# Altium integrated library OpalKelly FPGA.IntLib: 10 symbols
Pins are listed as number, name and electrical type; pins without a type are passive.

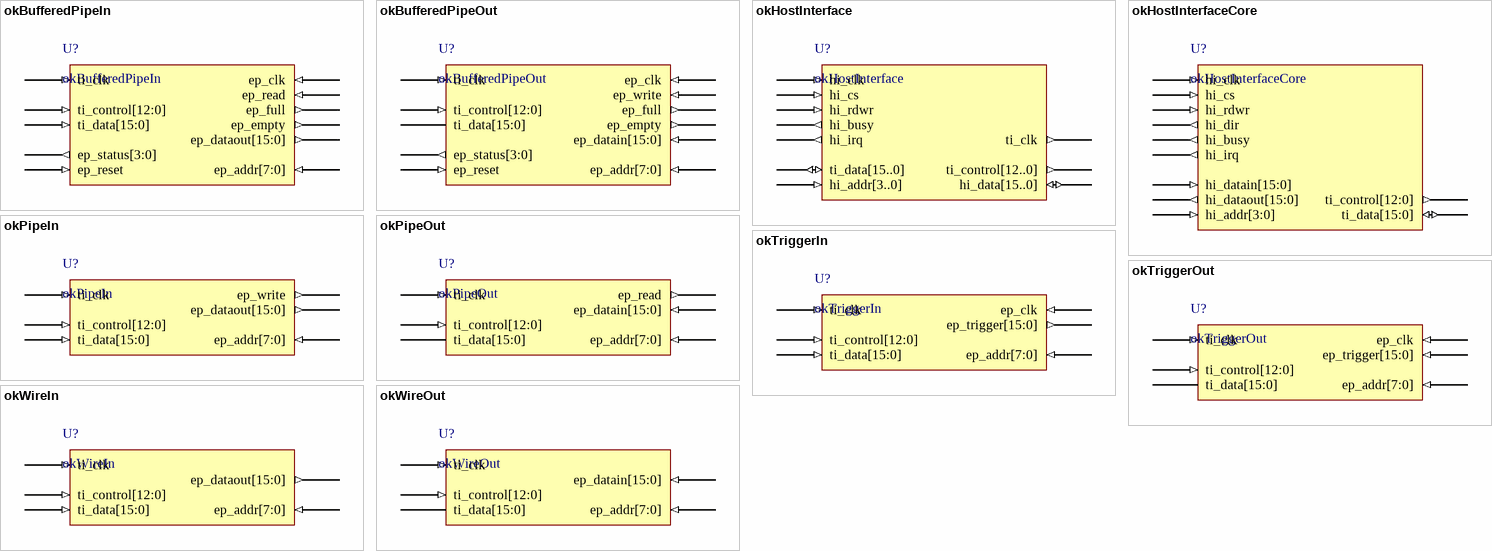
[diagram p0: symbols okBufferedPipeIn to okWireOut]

## okBufferedPipeIn
designator U?
Opal Kelly FPGA Board Buffered Pipe Input Interface
pins: ep_addr[7:0] (in), ep_clk (in), ep_dataout[15:0] (out), ep_empty (out), ep_full (out), ep_read (in), ep_reset (in), ep_status[3:0] (out), ti_clk (in), ti_control[12:0] (in), ti_data[15:0] (in)

## okBufferedPipeOut
designator U?
Opal Kelly FPGA Board Buffered Pipe Output Interface
pins: ep_addr[7:0] (in), ep_clk (in), ep_datain[15:0] (in), ep_empty (out), ep_full (out), ep_reset (in), ep_status[3:0] (out), ep_write (in), ti_clk (in), ti_control[12:0] (in), ti_data[15:0] (hiz)

## okHostInterface
designator U?
Opal Kelly FPGA Board Host Interface
pins: hi_addr[3..0] (in), hi_busy (out), hi_clk (in), hi_cs (in), hi_data[15..0] (io), hi_irq (out), hi_rdwr (in), ti_clk (out), ti_control[12..0] (out), ti_data[15..0] (io)

## okHostInterfaceCore
designator U?
Opal Kelly FPGA Board Host Interface Core
pins: hi_addr[3:0] (in), hi_busy (out), hi_clk (in), hi_cs (in), hi_datain[15:0] (in), hi_dataout[15:0] (out), hi_dir (out), hi_irq (out), hi_rdwr (in), ti_control[12:0] (out), ti_data[15:0] (io)

## okPipeIn
designator U?
Opal Kelly FPGA Board Pipe Input Interface
pins: ep_addr[7:0] (in), ep_dataout[15:0] (out), ep_write (out), ti_clk (in), ti_control[12:0] (in), ti_data[15:0] (in)

## okPipeOut
designator U?
Opal Kelly FPGA Board Pipe Output Interface
pins: ep_addr[7:0] (in), ep_datain[15:0] (in), ep_read (out), ti_clk (in), ti_control[12:0] (in), ti_data[15:0] (hiz)

## okTriggerIn
designator U?
Opal Kelly FPGA Board Trigger Input Interface
pins: ep_addr[7:0] (in), ep_clk (in), ep_trigger[15:0] (out), ti_clk (in), ti_control[12:0] (in), ti_data[15:0] (in)

## okTriggerOut
designator U?
Opal Kelly FPGA Board Trigger Output Interface
pins: ep_addr[7:0] (in), ep_clk (in), ep_trigger[15:0] (in), ti_clk (in), ti_control[12:0] (in), ti_data[15:0] (hiz)

## okWireIn
designator U?
Opal Kelly FPGA Board Wire Input Interface
pins: ep_addr[7:0] (in), ep_dataout[15:0] (out), ti_clk (in), ti_control[12:0] (in), ti_data[15:0] (in)

## okWireOut
designator U?
Opal Kelly FPGA Board Wire Output Interface
pins: ep_addr[7:0] (in), ep_datain[15:0] (in), ti_clk (in), ti_control[12:0] (in), ti_data[15:0] (hiz)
